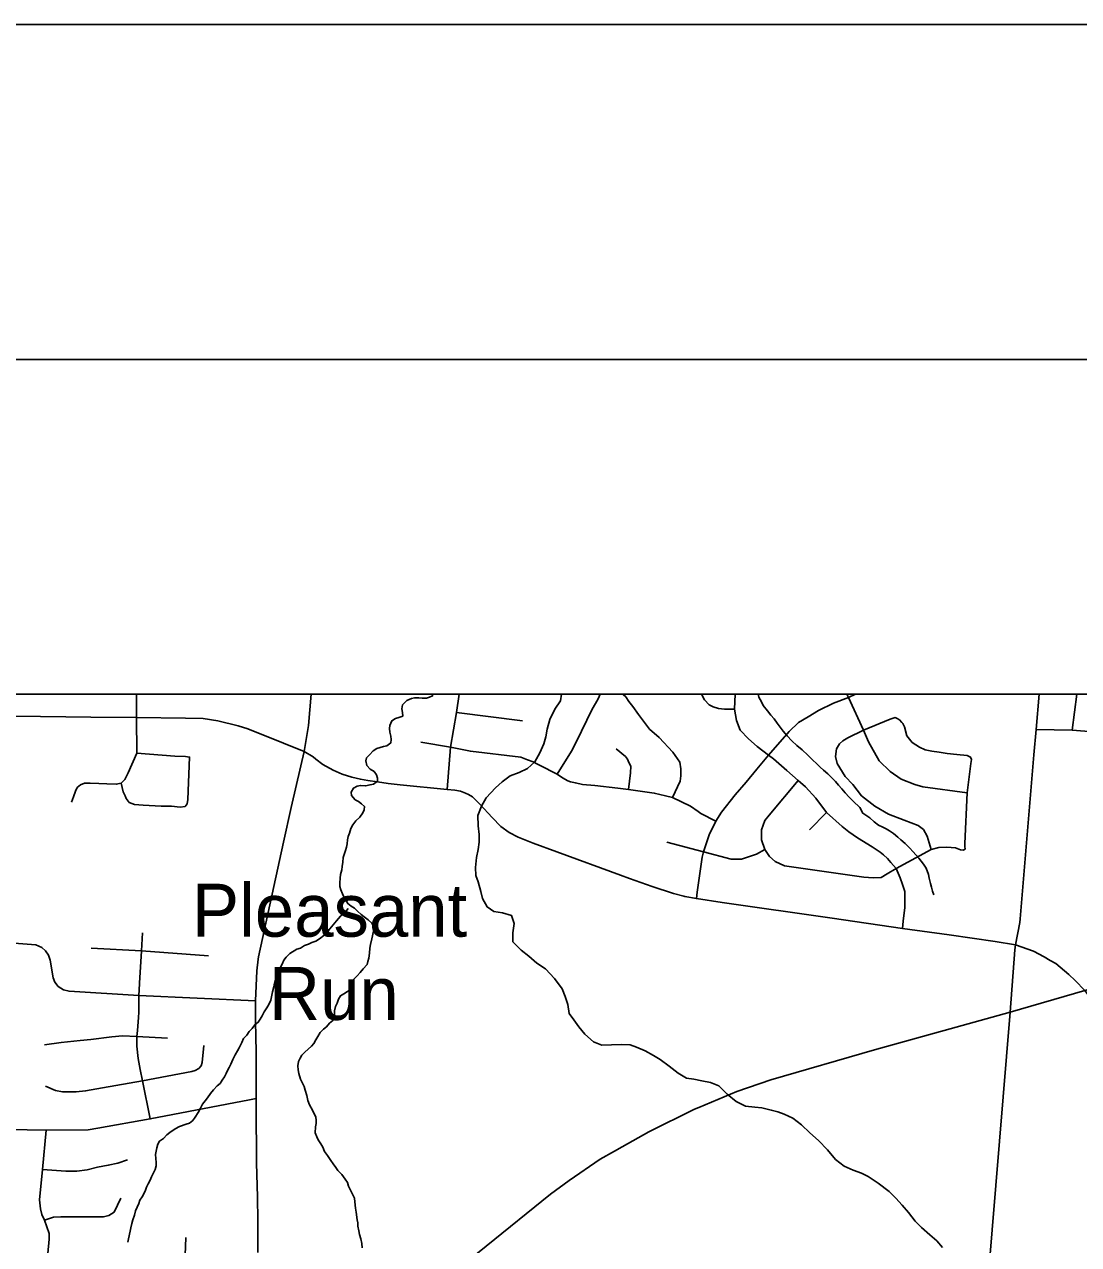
# Model space of a CAD drawing. Extents: x 0 to 69.5, y -4.5 to 22.
# Drawn here: x 5.399 to 6.973, y 20.179 to 22 of the extents above; entities that cross this region are included whole.
import ezdxf

# ---------------------------------------------------------------- set-up
doc = ezdxf.new("R2010")
doc.units = 0
for name, color, linetype in [('GM_X_City_Street', 7, 'Continuous'), ('GM_X_County_Road', 7, 'Continuous'), ('GM_X_Interstate_Route', 7, 'Continuous'), ('GM_X_Minor_River', 7, 'Continuous'), ('GM_X_Township_Subdivision', 7, 'Continuous'), ('GM_X_Unincorporated_Text', 7, 'Continuous'), ('GM_X_US_Route', 7, 'Continuous'), ('SH_Border', 7, 'Continuous'), ('SH_Data', 7, 'Continuous')]:
    doc.layers.add(name, color=color, linetype=linetype)

msp = doc.modelspace()

# ---------------------------------------------------------------- linework, layer by layer
at = {"layer": 'GM_X_City_Street'}
for points in [[(6.3832, 20.6986), (6.3849, 20.6981), (6.4022, 20.695), (6.4405, 20.6893), (6.605, 20.6658), (6.7096, 20.6506), (6.7795, 20.6409), (6.8483, 20.6312), (6.8782, 20.6263), (6.9055, 20.6167), (6.9213, 20.6082), (6.9304, 20.6028)], [(6.4022, 20.695), (6.4035, 20.7049)], [(6.7096, 20.6506), (6.7109, 20.6612)], [(6.8782, 20.6263), (6.8849, 20.6592), (6.8854, 20.665)], [(6.7405, 19.0079), (6.7405, 19.0079), (6.7657, 19.288), (6.7742, 19.3827), (6.7997, 19.6706), (6.8028, 19.7088), (6.8332, 20.0742), (6.8703, 20.5257), (6.8776, 20.6185)], [(6.8776, 20.6185), (6.8782, 20.6263)], [(6.9304, 20.6028), (6.9384, 20.598), (6.9578, 20.5819), (6.9677, 20.5727), (6.9821, 20.5579), (6.9976, 20.5368), (7.0156, 20.5042), (7.0369, 20.4622), (7.0524, 20.431), (7.0619, 20.4131), (7.0736, 20.3904)], [(5.7352, 20.3947), (5.7449, 20.3966)]]:
    msp.add_lwpolyline(points, dxfattribs=at)
at = {"layer": 'GM_X_County_Road'}
for points in [[(6.8854, 20.665), (6.9059, 20.9098), (6.9091, 20.9473), (6.9137, 21)], [(5.3429, 20.9683), (5.3857, 20.9676), (5.4981, 20.9661), (5.5663, 20.9653), (5.6398, 20.9643), (5.6661, 20.9637), (5.6877, 20.9605), (5.7182, 20.9531), (5.7325, 20.9484), (5.786, 20.9271), (5.8166, 20.9148)], [(5.8166, 20.9148), (5.8302, 20.9069), (5.8343, 20.9031), (5.8448, 20.8953), (5.8598, 20.8869), (5.8736, 20.881), (5.8879, 20.8765), (5.9007, 20.8732), (5.9118, 20.8713), (5.926, 20.8693), (5.942, 20.8668), (5.9602, 20.8648), (6.0301, 20.8581), (6.0417, 20.8568), (6.0502, 20.8553), (6.0573, 20.8526), (6.0618, 20.8504), (6.0678, 20.8469), (6.0791, 20.8358), (6.0974, 20.8159), (6.1102, 20.8027), (6.1228, 20.7937), (6.1362, 20.7869), (6.1585, 20.7779), (6.194, 20.7649), (6.2889, 20.7299), (6.3022, 20.7249), (6.3362, 20.7129), (6.3678, 20.7026), (6.3832, 20.6986)], [(5.375, 20.3502), (5.4319, 20.3493), (5.4945, 20.35), (5.5087, 20.3522), (5.5871, 20.3662), (5.7352, 20.3947)]]:
    msp.add_lwpolyline(points, dxfattribs=at)
at = {"layer": 'GM_X_Interstate_Route'}
for points in [[(6.4056, 20.3832), (6.4626, 20.4073), (6.5132, 20.4247), (6.6681, 20.4691), (6.8703, 20.5257), (6.9821, 20.5579), (7.3247, 20.6555), (7.624, 20.7407), (7.6888, 20.7597), (7.7242, 20.769), (7.855, 20.8068), (7.91, 20.8216)], [(6.2913, 20.3246), (6.3311, 20.3471), (6.3995, 20.3807), (6.4056, 20.3832)], [(5.8297, 19.9667), (5.8374, 19.973), (5.8497, 19.9841), (5.9922, 20.0984), (6.1844, 20.2537), (6.2121, 20.2744), (6.2584, 20.306), (6.2797, 20.318), (6.2913, 20.3246)]]:
    msp.add_lwpolyline(points, dxfattribs=at)
at = {"layer": 'GM_X_Minor_River'}
for points in [[(5.9698, 20.9909), (5.9636, 20.9842), (5.9627, 20.9781), (5.9637, 20.9728), (5.964, 20.9674), (5.9579, 20.9653), (5.9533, 20.9638), (5.9475, 20.9605), (5.9444, 20.9534), (5.9439, 20.9488), (5.9445, 20.9435), (5.9459, 20.9377), (5.9466, 20.9324), (5.9461, 20.9275), (5.9403, 20.923), (5.9354, 20.922), (5.9254, 20.9191), (5.9197, 20.9158), (5.9142, 20.9099), (5.91, 20.9054), (5.9087, 20.9005), (5.9101, 20.894), (5.9153, 20.8885), (5.921, 20.8846), (5.9246, 20.8796), (5.9261, 20.875), (5.9264, 20.8704), (5.9202, 20.866), (5.9152, 20.8649), (5.9084, 20.8632), (5.9008, 20.8641), (5.8958, 20.8631), (5.8905, 20.8601), (5.8869, 20.8537), (5.8876, 20.8488), (5.8928, 20.8426), (5.8977, 20.8398), (5.9021, 20.8367), (5.9066, 20.8324), (5.9061, 20.8275), (5.9045, 20.8229), (5.8998, 20.8166), (5.894, 20.8114), (5.8894, 20.805), (5.8866, 20.7997), (5.8846, 20.7929), (5.8822, 20.788), (5.8813, 20.7827), (5.8808, 20.7766), (5.88, 20.7717), (5.8783, 20.7668), (5.8767, 20.7623), (5.8751, 20.7562), (5.8746, 20.7494), (5.8737, 20.7429), (5.8728, 20.738), (5.8712, 20.7308), (5.8703, 20.7255), (5.8698, 20.7187), (5.8701, 20.7133), (5.8715, 20.708), (5.874, 20.7022), (5.8762, 20.6976), (5.8795, 20.6922), (5.8821, 20.6876), (5.8869, 20.6837), (5.8918, 20.6806), (5.8963, 20.6763), (5.9018, 20.6712), (5.9063, 20.6677), (5.9123, 20.6634), (5.9175, 20.6584), (5.9208, 20.653), (5.9203, 20.6465), (5.9178, 20.6348), (5.9158, 20.6268), (5.9149, 20.6211), (5.9144, 20.6136), (5.9131, 20.6064), (5.9118, 20.6014), (5.9106, 20.5965), (5.9048, 20.5902), (5.9001, 20.5846), (5.8958, 20.5797), (5.89, 20.5737), (5.888, 20.5688), (5.8875, 20.5639), (5.8859, 20.5594), (5.8813, 20.5564), (5.8759, 20.5531), (5.8709, 20.5501), (5.8678, 20.5449), (5.8658, 20.5388), (5.8634, 20.5339), (5.8621, 20.5275), (5.862, 20.5222), (5.8615, 20.5176), (5.8596, 20.5131), (5.8545, 20.509), (5.8503, 20.5038), (5.8456, 20.5004)], [(6.0085, 21), (6.0083, 20.9977), (6.0037, 20.9959), (5.9991, 20.9945), (5.993, 20.9942), (5.9877, 20.9947), (5.9816, 20.9948), (5.9771, 20.9938), (5.9698, 20.9909)], [(6.201, 21), (6.1994, 20.9904), (6.1911, 20.9777), (6.1832, 20.9626), (6.1794, 20.9479), (6.1772, 20.9365), (6.1743, 20.9263), (6.1687, 20.9128), (6.1612, 20.8993), (6.1503, 20.8893), (6.1376, 20.8831), (6.1242, 20.8781), (6.1123, 20.8696), (6.1022, 20.8604), (6.0885, 20.8455), (6.0814, 20.8331), (6.0761, 20.8191), (6.0765, 20.8039), (6.0781, 20.7906), (6.0778, 20.7792), (6.0764, 20.7686), (6.0739, 20.7564), (6.0727, 20.7413), (6.0732, 20.7298), (6.0764, 20.7199), (6.0806, 20.7057), (6.083, 20.6954), (6.0899, 20.6827), (6.1, 20.6756), (6.1129, 20.6737), (6.1261, 20.67), (6.1303, 20.6577), (6.1281, 20.6441), (6.1282, 20.6304), (6.1408, 20.6183), (6.1519, 20.6093), (6.1642, 20.5987), (6.1769, 20.5904), (6.1906, 20.5757), (6.2016, 20.5602), (6.2063, 20.5487), (6.2102, 20.5372), (6.2121, 20.5238), (6.2191, 20.5141), (6.2265, 20.5037), (6.2357, 20.4928), (6.2487, 20.4815), (6.2611, 20.4762), (6.2755, 20.4767), (6.2904, 20.4774), (6.3033, 20.4768), (6.313, 20.4731), (6.3258, 20.4678), (6.3382, 20.4607), (6.3483, 20.4548), (6.3617, 20.4449), (6.3751, 20.4343), (6.3875, 20.4272), (6.3981, 20.4254), (6.4105, 20.4228), (6.4234, 20.4206), (6.4358, 20.4154), (6.448, 20.4033), (6.4614, 20.3923), (6.4753, 20.3852), (6.4893, 20.3837), (6.4999, 20.3827), (6.5139, 20.3793), (6.5237, 20.3768), (6.5334, 20.3731), (6.5462, 20.3675), (6.5589, 20.3573), (6.5715, 20.3456)], [(6.4943, 21), (6.4956, 20.9956), (6.4993, 20.9887), (6.5018, 20.9833), (6.5085, 20.9756), (6.5133, 20.969), (6.5181, 20.9632), (6.5229, 20.957), (6.5274, 20.9508), (6.5318, 20.945), (6.5374, 20.9381), (6.5444, 20.9307), (6.5519, 20.9237), (6.5601, 20.9171), (6.5683, 20.9093), (6.5757, 20.9023), (6.5821, 20.8961), (6.5869, 20.8915), (6.5921, 20.8868), (6.5981, 20.8813), (6.61, 20.8697), (6.6144, 20.8643), (6.6193, 20.8589), (6.6241, 20.8531), (6.63, 20.8465), (6.636, 20.8403), (6.646, 20.8309), (6.6508, 20.8225), (6.6609, 20.8154), (6.6676, 20.8096), (6.674, 20.8049), (6.6804, 20.8017), (6.6853, 20.7993), (6.6905, 20.7962), (6.6965, 20.7923), (6.7029, 20.7868), (6.7073, 20.7829), (6.7137, 20.7771), (6.7204, 20.7709), (6.7259, 20.7647)], [(6.7259, 20.7647), (6.7341, 20.7554), (6.7411, 20.7465), (6.7452, 20.7407), (6.7484, 20.7308), (6.7498, 20.7254), (6.7516, 20.7178), (6.753, 20.712), (6.7548, 20.7063), (6.7565, 20.7009)], [(5.8823, 20.6804), (5.8784, 20.6755), (5.8711, 20.6688), (5.8652, 20.6617), (5.8598, 20.6561), (5.8551, 20.6497), (5.8512, 20.6449), (5.8462, 20.64), (5.8396, 20.6352), (5.8342, 20.6315), (5.8281, 20.6293), (5.8231, 20.6272), (5.8174, 20.625), (5.8113, 20.6213), (5.8059, 20.6195), (5.7955, 20.6129), (5.7901, 20.6077), (5.7866, 20.6032), (5.7838, 20.5971), (5.7807, 20.5915), (5.7783, 20.5866), (5.7759, 20.5806), (5.7739, 20.5749), (5.7726, 20.5688), (5.7714, 20.5632), (5.7697, 20.556), (5.7685, 20.5507), (5.7672, 20.5435), (5.764, 20.5371), (5.7612, 20.5318), (5.7569, 20.5258), (5.7542, 20.5201), (5.751, 20.5149), (5.7483, 20.5104), (5.7429, 20.5067), (5.739, 20.5014), (5.7347, 20.4966), (5.7312, 20.4913), (5.7262, 20.4861), (5.7238, 20.4804), (5.7198, 20.4725), (5.7171, 20.4676), (5.7139, 20.462), (5.7103, 20.4548), (5.7072, 20.4477), (5.7048, 20.4432), (5.7024, 20.4386), (5.7004, 20.4341), (5.6977, 20.4292), (5.6942, 20.424), (5.6914, 20.4191), (5.6868, 20.4158), (5.6813, 20.4098), (5.6767, 20.4042), (5.6724, 20.3978), (5.6692, 20.3933), (5.665, 20.388), (5.6618, 20.3824), (5.6583, 20.376), (5.6543, 20.3689), (5.6508, 20.364), (5.6458, 20.3599), (5.6405, 20.3585), (5.6305, 20.3549), (5.624, 20.3516), (5.6163, 20.346), (5.6117, 20.3423), (5.607, 20.3371), (5.6008, 20.333), (5.5985, 20.3285), (5.5968, 20.3232), (5.596, 20.3183), (5.5951, 20.313), (5.5954, 20.3069), (5.596, 20.3012), (5.5959, 20.2962), (5.5943, 20.2909), (5.5919, 20.2857), (5.5888, 20.2796), (5.5868, 20.2747), (5.584, 20.2695), (5.5816, 20.2642), (5.58, 20.2597), (5.5772, 20.2544), (5.5752, 20.2499), (5.5717, 20.245), (5.5701, 20.2397), (5.5673, 20.2344), (5.5649, 20.2288), (5.5633, 20.2223), (5.5609, 20.2155), (5.5593, 20.2099), (5.558, 20.2034), (5.5571, 20.1985), (5.5546, 20.1871), (5.5538, 20.1822)], [(5.8456, 20.5004), (5.8406, 20.4952), (5.8371, 20.4892), (5.8343, 20.4843), (5.8312, 20.479), (5.8277, 20.4746), (5.8226, 20.4705), (5.8176, 20.466), (5.8133, 20.4615), (5.8106, 20.457), (5.8082, 20.4517), (5.8073, 20.4453), (5.8076, 20.4396), (5.809, 20.4339), (5.8115, 20.4254), (5.8166, 20.4147), (5.818, 20.4093), (5.8205, 20.4013), (5.8222, 20.3936), (5.8248, 20.3871), (5.8291, 20.3791), (5.8317, 20.3737), (5.8343, 20.3691), (5.8349, 20.3637), (5.8348, 20.3592), (5.8336, 20.3542), (5.8334, 20.3455), (5.8356, 20.3394), (5.8374, 20.3348), (5.8414, 20.329), (5.8447, 20.324), (5.8473, 20.3178), (5.8517, 20.3117), (5.8565, 20.3043), (5.8598, 20.2993), (5.8642, 20.2939), (5.8672, 20.2893), (5.8731, 20.2831), (5.8779, 20.2765), (5.8812, 20.2711), (5.8827, 20.2658), (5.8859, 20.2596), (5.8896, 20.2527), (5.8918, 20.2481), (5.8924, 20.2424), (5.8934, 20.2329), (5.8944, 20.2271), (5.8957, 20.2157), (5.8967, 20.2111), (5.897, 20.2062), (5.8984, 20.1993), (5.8994, 20.1936), (5.9012, 20.1871), (5.9026, 20.1802), (5.9032, 20.1737)], [(6.5715, 20.3456), (6.5845, 20.3339), (6.5978, 20.3202), (6.61, 20.3055), (6.6227, 20.2957), (6.6362, 20.2897), (6.6486, 20.2852), (6.6587, 20.28), (6.6737, 20.2701), (6.6897, 20.258), (6.6997, 20.2478), (6.7093, 20.2373), (6.7186, 20.2265), (6.7289, 20.2137), (6.7382, 20.2039), (6.7508, 20.1934), (6.7608, 20.184), (6.7693, 20.1743)]]:
    msp.add_lwpolyline(points, dxfattribs=at)
at = {"layer": 'GM_X_Township_Subdivision'}
for points in [[(5.4694, 20.839), (5.4724, 20.8471), (5.4753, 20.8553), (5.4781, 20.8608), (5.4828, 20.8647), (5.4887, 20.8673), (5.4971, 20.8675), (5.5105, 20.8671), (5.5223, 20.8663), (5.5364, 20.8657), (5.5437, 20.8675), (5.549, 20.8728), (5.5539, 20.883), (5.5672, 20.9123), (5.5663, 20.9653), (5.5663, 21)], [(6.0301, 20.8581), (6.0354, 20.9212), (6.044, 20.9727), (6.0481, 21)], [(6.1944, 20.8806), (6.2157, 20.9151), (6.2234, 20.9297), (6.2461, 20.9768), (6.2558, 20.9934), (6.2586, 21)], [(6.3666, 20.8461), (6.3777, 20.8706), (6.3789, 20.8785), (6.3788, 20.8888), (6.3773, 20.8987), (6.367, 20.9136), (6.3464, 20.9354), (6.3323, 20.9481), (6.3157, 20.97), (6.3074, 20.9818), (6.3015, 20.9895), (6.2966, 20.9964), (6.2929, 20.9997), (6.2925, 21)], [(6.4035, 20.7049), (6.4107, 20.7567), (6.413, 20.7651), (6.4213, 20.7905), (6.431, 20.8109), (6.4396, 20.8241), (6.46, 20.85), (6.4764, 20.8687), (6.4923, 20.8885), (6.5099, 20.909), (6.5406, 20.9444), (6.5548, 20.9578), (6.5688, 20.9666), (6.5846, 20.9759), (6.607, 20.9866), (6.6294, 20.9953), (6.6397, 21)], [(6.459, 20.9777), (6.444, 20.9779), (6.4354, 20.9788), (6.4271, 20.9814), (6.4214, 20.9845), (6.4142, 20.9919), (6.4098, 21)], [(6.4602, 21), (6.459, 20.9777), (6.462, 20.9607), (6.4676, 20.9467), (6.4798, 20.9337), (6.4931, 20.922), (6.5099, 20.909), (6.5171, 20.9035), (6.5373, 20.8862), (6.5542, 20.8716), (6.5651, 20.8617), (6.5803, 20.8449), (6.5963, 20.8235), (6.6198, 20.8025), (6.6297, 20.7945), (6.6426, 20.786), (6.6644, 20.7724), (6.6764, 20.7646), (6.6813, 20.7603), (6.6875, 20.755), (6.6926, 20.749), (6.7001, 20.7401), (6.7061, 20.7263), (6.7098, 20.7161), (6.7131, 20.7057), (6.7134, 20.682), (6.7109, 20.6612)], [(6.8063, 20.853), (6.7402, 20.8617), (6.7281, 20.8656), (6.7077, 20.8734), (6.6913, 20.8848), (6.6748, 20.9006), (6.6588, 20.929), (6.6515, 20.9464), (6.6294, 20.9953), (6.6269, 21)], [(6.9091, 20.9473), (6.963, 20.9464), (7.0256, 20.9416), (7.061, 20.9337), (7.0802, 20.9306), (7.0895, 20.9304), (7.1023, 20.9323), (7.1174, 20.9395), (7.1268, 20.9457), (7.1446, 20.9641), (7.1673, 20.9877), (7.1788, 21)], [(6.963, 20.9464), (6.9702, 21)], [(6.044, 20.9727), (6.1425, 20.9606)], [(6.7524, 20.7685), (6.7513, 20.7735), (6.7467, 20.7881), (6.7412, 20.798), (6.7333, 20.8043), (6.7121, 20.8123), (6.6889, 20.8212), (6.6683, 20.8331), (6.6484, 20.8486), (6.6358, 20.8652), (6.6244, 20.8773), (6.6121, 20.8965), (6.6098, 20.907), (6.6113, 20.9187), (6.6158, 20.9261), (6.6205, 20.9306), (6.6283, 20.935), (6.6515, 20.9464), (6.6915, 20.9631), (6.6987, 20.9652), (6.702, 20.9637), (6.7055, 20.9617), (6.7087, 20.9579)], [(6.7087, 20.9579), (6.7102, 20.9564), (6.7127, 20.9514), (6.7164, 20.9382), (6.7241, 20.9282), (6.7351, 20.9212), (6.7435, 20.9171), (6.7536, 20.915), (6.7645, 20.9136), (6.7766, 20.9117), (6.791, 20.9101), (6.8064, 20.9085), (6.8113, 20.9063), (6.8128, 20.9027), (6.8118, 20.8965), (6.8063, 20.853), (6.803, 20.7773), (6.803, 20.7726), (6.8031, 20.7689)], [(6.164, 20.8963), (6.1586, 20.8994), (6.1502, 20.9024), (6.1399, 20.9061), (6.0649, 20.9151), (6.0354, 20.9212), (5.991, 20.9287)], [(5.5437, 20.8675), (5.5468, 20.8542), (5.5495, 20.8485), (5.5513, 20.8444), (5.5556, 20.8384), (5.5633, 20.8357), (5.5765, 20.8345), (5.6032, 20.8331), (5.6187, 20.8329), (5.6317, 20.8317), (5.6389, 20.8325), (5.6423, 20.8365), (5.6431, 20.8431), (5.6458, 20.9064), (5.6397, 20.907), (5.6238, 20.9078), (5.5672, 20.9123)], [(6.3007, 20.8578), (6.3037, 20.883), (6.3041, 20.8929), (6.3014, 20.8982), (6.2991, 20.9031), (6.2963, 20.9074), (6.2826, 20.9184)], [(6.405, 20.8249), (6.3933, 20.833), (6.3666, 20.8461), (6.3563, 20.8485), (6.3393, 20.8525), (6.3007, 20.8578), (6.2851, 20.86), (6.2504, 20.8637), (6.2323, 20.8655), (6.2215, 20.8677), (6.2145, 20.8695), (6.2104, 20.8707), (6.2024, 20.8752), (6.1944, 20.8806), (6.1679, 20.8941), (6.164, 20.8963)], [(6.5542, 20.8716), (6.5108, 20.8195), (6.5042, 20.8115), (6.4994, 20.7975), (6.4991, 20.783), (6.5041, 20.7686), (6.5114, 20.7579), (6.5196, 20.7505), (6.5339, 20.7442), (6.652, 20.7272), (6.666, 20.7259), (6.678, 20.7267), (6.687, 20.7322), (6.7001, 20.7401), (6.7524, 20.7685), (6.7642, 20.7715), (6.7762, 20.7716), (6.7889, 20.7709), (6.7962, 20.7678), (6.8005, 20.7672), (6.8031, 20.7689)], [(6.431, 20.8109), (6.4089, 20.8222), (6.405, 20.8249)], [(6.5712, 20.7976), (6.5963, 20.8235)], [(6.3578, 20.7792), (6.413, 20.7651), (6.454, 20.7537), (6.4697, 20.7537), (6.492, 20.7616), (6.5041, 20.7686)], [(5.5757, 20.644), (5.5741, 20.6169), (5.5712, 20.5688)], [(5.7442, 20.5423), (5.5702, 20.5504), (5.4658, 20.5568), (5.4576, 20.5588), (5.4496, 20.5641), (5.4445, 20.5703), (5.4423, 20.5768), (5.4376, 20.6034), (5.4352, 20.6107), (5.4308, 20.617), (5.4252, 20.6223), (5.4165, 20.6261), (5.3647, 20.6298), (5.3631, 20.6296)], [(5.4987, 20.621), (5.5741, 20.6169), (5.6742, 20.6095)], [(5.5712, 20.5688), (5.5712, 20.5677), (5.5702, 20.5504), (5.5698, 20.5257)], [(5.5698, 20.5257), (5.5697, 20.5178), (5.5682, 20.498), (5.5671, 20.489), (5.5672, 20.4749), (5.5689, 20.4562), (5.572, 20.4402), (5.5754, 20.4229), (5.5871, 20.3662)], [(5.4292, 20.477), (5.4539, 20.4803), (5.4823, 20.4834), (5.4981, 20.4849), (5.5297, 20.4887), (5.5454, 20.4903), (5.5671, 20.489), (5.6126, 20.4866)], [(5.4308, 20.4152), (5.4456, 20.4088), (5.4563, 20.4068), (5.4765, 20.4068), (5.4905, 20.4079), (5.5157, 20.4124), (5.5754, 20.4229), (5.6489, 20.4368), (5.6541, 20.4385), (5.6595, 20.4414), (5.6628, 20.4455), (5.6644, 20.4504), (5.6668, 20.4756)], [(5.4362, 20.193), (5.4362, 20.1953), (5.4292, 20.2149), (5.425, 20.2233), (5.423, 20.232), (5.4215, 20.2455), (5.426, 20.2908), (5.4319, 20.3493)], [(5.426, 20.2908), (5.4611, 20.288), (5.4775, 20.288), (5.4927, 20.2903), (5.5081, 20.294), (5.5243, 20.297), (5.5384, 20.3002), (5.5529, 20.3049)], [(5.4292, 20.2149), (5.4427, 20.2196), (5.4536, 20.2199), (5.5173, 20.2201), (5.5253, 20.2218), (5.533, 20.2271), (5.5432, 20.248)], [(5.6551, 20.116), (5.6413, 20.1054), (5.6314, 20.0955), (5.6217, 20.085), (5.6112, 20.0715), (5.5905, 20.044), (5.5797, 20.0265), (5.5633, 20), (5.5497, 19.9764), (5.547, 19.9724), (5.5436, 19.9704), (5.5382, 19.9696), (5.4722, 19.9699), (5.4324, 19.9701), (5.4245, 19.9734), (5.4197, 19.977), (5.418, 19.9823), (5.4242, 20.0517), (5.4344, 20.1652), (5.4363, 20.1866), (5.4362, 20.1924), (5.4362, 20.193)], [(5.6918, 20.0681), (5.6551, 20.116), (5.6522, 20.1198), (5.6467, 20.1298), (5.6422, 20.1426), (5.6393, 20.163), (5.6403, 20.1891)]]:
    msp.add_lwpolyline(points, dxfattribs=at)
at = {"layer": 'GM_X_US_Route'}
for points in [[(5.8166, 20.9148), (5.8233, 20.9535), (5.8273, 21)], [(5.7986, 20.8375), (5.8166, 20.9148)], [(5.7859, 20.7794), (5.7971, 20.8309), (5.7986, 20.8375)], [(5.7482, 20.6048), (5.7486, 20.6081), (5.7859, 20.7794)], [(5.7439, 20.5157), (5.7442, 20.5423), (5.746, 20.5874), (5.7482, 20.6048)], [(5.7449, 20.4661), (5.744, 20.5116), (5.7439, 20.5155), (5.7439, 20.5157)], [(5.745, 20.3774), (5.7449, 20.3966), (5.7452, 20.4494), (5.7449, 20.4661)], [(5.7456, 20.3008), (5.7454, 20.308), (5.745, 20.3774)], [(5.7474, 20.2147), (5.7471, 20.2495), (5.7456, 20.3008)], [(5.7476, 20.1668), (5.7477, 20.1736), (5.7474, 20.2147)]]:
    msp.add_lwpolyline(points, dxfattribs=at)
at = {"layer": 'SH_Border'}
msp.add_lwpolyline([(1.5, 21.5), (33.5, 21.5), (33.5, 0.5), (1.5, 0.5)], close=True, dxfattribs=at)
at = {"layer": 'SH_Data'}
msp.add_line((2, 21), (8.8, 21), dxfattribs=at)
msp.add_lwpolyline([(0, 0), (34, 0), (34, 22), (0, 22)], close=True, dxfattribs=at)

# ---------------------------------------------------------------- texts
at = {"layer": 'GM_X_Unincorporated_Text'}
for s, p in [('Pleasant', (5.6492, 20.6382)), ('Run', (5.7642, 20.514))]:
    msp.add_text(s, height=0.07898, rotation=0, dxfattribs=at).set_placement(p)

doc.saveas('drawing.dxf')
